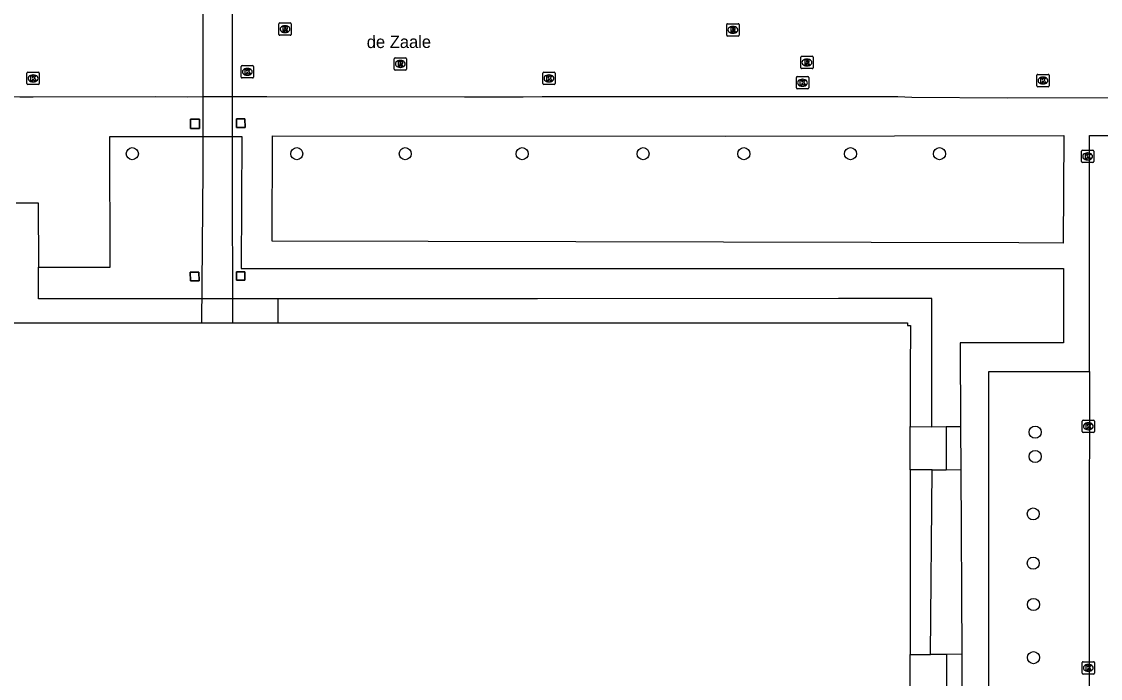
# Model space of a CAD drawing. Extents: x 161477 to 163040, y 383680 to 384868.
# Drawn here: x 161935.3 to 162022.7, y 384324.8 to 384378 of the extents above; entities that cross this region are included whole.
import ezdxf

# ---------------------------------------------------------------- set-up
doc = ezdxf.new("R2010")
doc.units = 0
for name, color, linetype in [('IMGEO_Boom', 7, 'Continuous'), ('IMGEO_Dek', 7, 'Continuous'), ('IMGEO_Groenvoorziening', 7, 'Continuous'), ('IMGEO_Kolk', 7, 'Continuous'), ('IMGEO_Openbare_ruimte_label', 7, 'Continuous'), ('IMGEO_Pand', 7, 'Continuous'), ('IMGEO_Pijler', 7, 'Continuous'), ('IMGEO_Rijbaan_lokaal_open', 7, 'Continuous'), ('IMGEO_Rioolput', 7, 'Continuous'), ('IMGEO_Voetpad_gesloten', 7, 'Continuous'), ('IMGEO_Voetpad_op_trap', 7, 'Continuous'), ('IMGEO_Voetpad_open', 7, 'Continuous')]:
    doc.layers.add(name, color=color, linetype=linetype)

msp = doc.modelspace()

# ---------------------------------------------------------------- linework, layer by layer
at = {"layer": 'IMGEO_Boom'}
for centre in [(161944.3, 384367.33), (161957.61, 384367.33), (161966.39, 384367.33), (161975.85, 384367.33), (161985.64, 384367.33), (161993.79, 384367.33), (162002.43, 384367.33), (162009.63, 384367.33), (162017.37, 384344.77), (162017.37, 384342.8), (162017.22, 384338.15), (162017.22, 384334.16), (162017.24, 384330.81), (162017.24, 384326.51)]:
    msp.add_circle(centre, 0.489, dxfattribs=at)
at = {"layer": 'IMGEO_Dek'}
msp.add_lwpolyline([(161952.4, 384381.825), (161952.383, 384398.52), (161949.962, 384398.52), (161949.996, 384381.818), (161950.004, 384371.924), (161950.007, 384368.834), (161950.009, 384366.051), (161949.91, 384353.629), (161952.428, 384353.629), (161952.416, 384366.048), (161952.413, 384368.836), (161952.41, 384371.927)], close=True, dxfattribs=at)
at = {"layer": 'IMGEO_Groenvoorziening'}
for points in [[(161949.701, 384357.043), (161948.998, 384357.039), (161948.994, 384357.742), (161949.697, 384357.746), (161949.701, 384357.043)], [(161953.419, 384357.087), (161952.733, 384357.084), (161952.73, 384357.77), (161953.416, 384357.773), (161953.419, 384357.087)], [(162009.022, 384345.215), (162009.008, 384355.596), (162001.453, 384355.609), (161977.095, 384355.578), (161956.091, 384355.586)], [(162008.905, 384326.757), (162009.025, 384341.729)]]:
    msp.add_lwpolyline(points, dxfattribs=at)
at = {"layer": 'IMGEO_Kolk'}
for p, q in [((161935.771, 384373.006), (161935.771, 384373.858)), ((161935.846, 384373.932), (161936.698, 384373.932)), ((161936.772, 384373.858), (161936.772, 384373.006)), ((161953.108, 384373.537), (161953.108, 384374.389)), ((161953.183, 384374.463), (161954.035, 384374.463)), ((161953.596, 384374.243), (161953.621, 384374.243)), ((161954.109, 384374.389), (161954.109, 384373.537)), ((161977.522, 384373.006), (161977.522, 384373.858)), ((161977.597, 384373.932), (161978.449, 384373.932)), ((161978.523, 384373.858), (161978.523, 384373.006)), ((161936.698, 384372.932), (161935.846, 384372.932)), ((161936.282, 384373.152), (161936.257, 384373.152)), ((161936.259, 384373.712), (161936.284, 384373.712)), ((161954.035, 384373.463), (161953.183, 384373.463)), ((161953.619, 384373.683), (161953.594, 384373.683)), ((161978.449, 384372.932), (161977.597, 384372.932)), ((161978.033, 384373.152), (161978.008, 384373.152)), ((161978.01, 384373.712), (161978.035, 384373.712)), ((161998.044, 384372.653), (161998.044, 384373.505)), ((161998.119, 384373.579), (161998.971, 384373.579)), ((161998.532, 384373.359), (161998.557, 384373.359)), ((161999.045, 384373.505), (161999.045, 384372.653)), ((162017.505, 384372.83), (162017.505, 384373.682)), ((162017.58, 384373.756), (162018.432, 384373.756)), ((162018.016, 384372.976), (162017.991, 384372.976)), ((162017.993, 384373.536), (162018.018, 384373.536)), ((162018.506, 384373.682), (162018.506, 384372.83)), ((161998.971, 384372.579), (161998.119, 384372.579)), ((161998.555, 384372.799), (161998.53, 384372.799)), ((162018.432, 384372.756), (162017.58, 384372.756)), ((162021.119, 384366.687), (162021.119, 384367.539)), ((162021.194, 384367.613), (162022.046, 384367.613)), ((162021.63, 384366.833), (162021.605, 384366.833)), ((162021.607, 384367.393), (162021.632, 384367.393)), ((162022.12, 384367.539), (162022.12, 384366.687)), ((162022.046, 384366.613), (162021.194, 384366.613)), ((162021.175, 384344.824), (162021.175, 384345.676)), ((162021.25, 384345.75), (162022.102, 384345.75)), ((162021.686, 384344.97), (162021.661, 384344.97)), ((162021.663, 384345.53), (162021.688, 384345.53)), ((162022.176, 384345.676), (162022.176, 384344.824)), ((162022.102, 384344.75), (162021.25, 384344.75)), ((162021.175, 384325.256), (162021.175, 384326.108)), ((162021.25, 384326.182), (162022.102, 384326.182)), ((162021.663, 384325.962), (162021.688, 384325.962)), ((162022.176, 384326.108), (162022.176, 384325.256)), ((162022.102, 384325.182), (162021.25, 384325.182)), ((162021.686, 384325.402), (162021.661, 384325.402))]:
    msp.add_line(p, q, dxfattribs=at)
for points in [[(161935.771, 384373.006), (161935.771, 384373.858)], [(161935.846, 384373.932), (161936.698, 384373.932)], [(161936.772, 384373.858), (161936.772, 384373.006)], [(161953.108, 384373.537), (161953.108, 384374.389)], [(161953.183, 384374.463), (161954.035, 384374.463)], [(161953.429, 384374.163), (161953.552, 384374.163), (161953.552, 384374.012), (161953.682, 384374.163), (161953.846, 384374.163), (161953.7, 384374.012), (161953.853, 384373.763), (161953.701, 384373.763), (161953.616, 384373.927), (161953.552, 384373.86), (161953.552, 384373.763), (161953.429, 384373.763), (161953.429, 384374.163)], [(161954.109, 384374.389), (161954.109, 384373.537)], [(161977.522, 384373.006), (161977.522, 384373.858)], [(161977.597, 384373.932), (161978.449, 384373.932)], [(161978.523, 384373.858), (161978.523, 384373.006)], [(161936.698, 384372.932), (161935.846, 384372.932)], [(161936.092, 384373.632), (161936.215, 384373.632), (161936.215, 384373.481), (161936.345, 384373.632), (161936.509, 384373.632), (161936.363, 384373.481), (161936.516, 384373.232), (161936.364, 384373.232), (161936.279, 384373.396), (161936.215, 384373.329), (161936.215, 384373.232), (161936.092, 384373.232), (161936.092, 384373.632)], [(161954.035, 384373.463), (161953.183, 384373.463)], [(161978.449, 384372.932), (161977.597, 384372.932)], [(161977.843, 384373.632), (161977.966, 384373.632), (161977.966, 384373.481), (161978.096, 384373.632), (161978.26, 384373.632), (161978.114, 384373.481), (161978.267, 384373.232), (161978.115, 384373.232), (161978.03, 384373.396), (161977.966, 384373.329), (161977.966, 384373.232), (161977.843, 384373.232), (161977.843, 384373.632)], [(161998.044, 384372.653), (161998.044, 384373.505)], [(161998.119, 384373.579), (161998.971, 384373.579)], [(161998.365, 384373.279), (161998.488, 384373.279), (161998.488, 384373.128), (161998.618, 384373.279), (161998.782, 384373.279), (161998.636, 384373.128), (161998.789, 384372.879), (161998.637, 384372.879), (161998.552, 384373.043), (161998.488, 384372.976), (161998.488, 384372.879), (161998.365, 384372.879), (161998.365, 384373.279)], [(161999.045, 384373.505), (161999.045, 384372.653)], [(162017.505, 384372.83), (162017.505, 384373.682)], [(162017.58, 384373.756), (162018.432, 384373.756)], [(162017.826, 384373.456), (162017.949, 384373.456), (162017.949, 384373.305), (162018.079, 384373.456), (162018.243, 384373.456), (162018.097, 384373.305), (162018.25, 384373.056), (162018.098, 384373.056), (162018.013, 384373.22), (162017.949, 384373.153), (162017.949, 384373.056), (162017.826, 384373.056), (162017.826, 384373.456)], [(162018.506, 384373.682), (162018.506, 384372.83)], [(161998.971, 384372.579), (161998.119, 384372.579)], [(162018.432, 384372.756), (162017.58, 384372.756)], [(162021.119, 384366.687), (162021.119, 384367.539)], [(162021.194, 384367.613), (162022.046, 384367.613)], [(162021.44, 384367.313), (162021.563, 384367.313), (162021.563, 384367.162), (162021.693, 384367.313), (162021.857, 384367.313), (162021.711, 384367.162), (162021.864, 384366.913), (162021.712, 384366.913), (162021.627, 384367.077), (162021.563, 384367.01), (162021.563, 384366.913), (162021.44, 384366.913), (162021.44, 384367.313)], [(162022.12, 384367.539), (162022.12, 384366.687)], [(162022.046, 384366.613), (162021.194, 384366.613)], [(162021.175, 384344.824), (162021.175, 384345.676)], [(162021.25, 384345.75), (162022.102, 384345.75)], [(162021.496, 384345.45), (162021.619, 384345.45), (162021.619, 384345.299), (162021.749, 384345.45), (162021.913, 384345.45), (162021.767, 384345.299), (162021.92, 384345.05), (162021.768, 384345.05), (162021.683, 384345.214), (162021.619, 384345.147), (162021.619, 384345.05), (162021.496, 384345.05), (162021.496, 384345.45)], [(162022.176, 384345.676), (162022.176, 384344.824)], [(162022.102, 384344.75), (162021.25, 384344.75)], [(162021.175, 384325.256), (162021.175, 384326.108)], [(162021.25, 384326.182), (162022.102, 384326.182)], [(162021.496, 384325.882), (162021.619, 384325.882), (162021.619, 384325.731), (162021.749, 384325.882), (162021.913, 384325.882), (162021.767, 384325.731), (162021.92, 384325.482), (162021.768, 384325.482), (162021.683, 384325.646), (162021.619, 384325.579), (162021.619, 384325.482), (162021.496, 384325.482), (162021.496, 384325.882)], [(162022.176, 384326.108), (162022.176, 384325.256)], [(162022.102, 384325.182), (162021.25, 384325.182)]]:
    msp.add_lwpolyline(points, dxfattribs=at)
for centre, start, end in [((161935.848, 384373.856), 91.55205, 178.44795), ((161935.848, 384373.856), 91.55205, 178.44795), ((161936.696, 384373.856), 1.55205, 88.44795), ((161936.696, 384373.856), 1.55205, 88.44795), ((161953.185, 384374.387), 91.55205, 178.44795), ((161953.185, 384374.387), 91.55205, 178.44795), ((161954.033, 384374.387), 1.55205, 88.44795), ((161954.033, 384374.387), 1.55205, 88.44795), ((161977.599, 384373.856), 91.55205, 178.44795), ((161977.599, 384373.856), 91.55205, 178.44795), ((161978.447, 384373.856), 1.55205, 88.44795), ((161978.447, 384373.856), 1.55205, 88.44795), ((161935.848, 384373.008), 181.55205, 268.44795), ((161935.848, 384373.008), 181.55205, 268.44795), ((161936.696, 384373.008), 271.55205, 358.44795), ((161936.696, 384373.008), 271.55205, 358.44795), ((161953.185, 384373.539), 181.55205, 268.44795), ((161953.185, 384373.539), 181.55205, 268.44795), ((161954.033, 384373.539), 271.55205, 358.44795), ((161954.033, 384373.539), 271.55205, 358.44795), ((161977.599, 384373.008), 181.55205, 268.44795), ((161977.599, 384373.008), 181.55205, 268.44795), ((161978.447, 384373.008), 271.55205, 358.44795), ((161978.447, 384373.008), 271.55205, 358.44795), ((161998.121, 384373.503), 91.55205, 178.44795), ((161998.121, 384373.503), 91.55205, 178.44795), ((161998.969, 384373.503), 1.55205, 88.44795), ((161998.969, 384373.503), 1.55205, 88.44795), ((162017.582, 384373.68), 91.55205, 178.44795), ((162017.582, 384373.68), 91.55205, 178.44795), ((162018.43, 384373.68), 1.55205, 88.44795), ((162018.43, 384373.68), 1.55205, 88.44795), ((161998.121, 384372.655), 181.55205, 268.44795), ((161998.121, 384372.655), 181.55205, 268.44795), ((161998.969, 384372.655), 271.55205, 358.44795), ((161998.969, 384372.655), 271.55205, 358.44795), ((162017.582, 384372.832), 181.55205, 268.44795), ((162017.582, 384372.832), 181.55205, 268.44795), ((162018.43, 384372.832), 271.55205, 358.44795), ((162018.43, 384372.832), 271.55205, 358.44795), ((162021.196, 384367.537), 91.55205, 178.44795), ((162021.196, 384367.537), 91.55205, 178.44795), ((162022.044, 384367.537), 1.55205, 88.44795), ((162022.044, 384367.537), 1.55205, 88.44795), ((162021.196, 384366.689), 181.55205, 268.44795), ((162021.196, 384366.689), 181.55205, 268.44795), ((162022.044, 384366.689), 271.55205, 358.44795), ((162022.044, 384366.689), 271.55205, 358.44795), ((162021.252, 384345.674), 91.55205, 178.44795), ((162021.252, 384345.674), 91.55205, 178.44795), ((162022.1, 384345.674), 1.55205, 88.44795), ((162022.1, 384345.674), 1.55205, 88.44795), ((162021.252, 384344.826), 181.55205, 268.44795), ((162021.252, 384344.826), 181.55205, 268.44795), ((162022.1, 384344.826), 271.55205, 358.44795), ((162022.1, 384344.826), 271.55205, 358.44795), ((162021.252, 384326.106), 91.55205, 178.44795), ((162021.252, 384326.106), 91.55205, 178.44795), ((162022.1, 384326.106), 1.55205, 88.44795), ((162022.1, 384326.106), 1.55205, 88.44795), ((162021.252, 384325.258), 181.55205, 268.44795), ((162021.252, 384325.258), 181.55205, 268.44795), ((162022.1, 384325.258), 271.55205, 358.44795), ((162022.1, 384325.258), 271.55205, 358.44795)]:
    msp.add_arc(centre, 0.0765, start, end, dxfattribs=at)
for centre, major_axis, ratio, start_param, end_param in [((161953.595, 384373.963), (-0.387, 0.002), 0.722429, 4.712389, 7.853982), ((161953.62, 384373.963), (-0.39, 0.002), 0.717154, 1.570796, 4.712389), ((161936.258, 384373.432), (-0.387, 0.002), 0.722429, 4.712389, 7.853982), ((161936.283, 384373.432), (-0.39, 0.002), 0.717154, 1.570796, 4.712389), ((161978.009, 384373.432), (-0.387, 0.002), 0.722429, 4.712389, 7.853982), ((161978.034, 384373.432), (-0.39, 0.002), 0.717154, 1.570796, 4.712389), ((161998.531, 384373.079), (-0.387, 0.002), 0.722429, 4.712389, 7.853982), ((161998.556, 384373.079), (-0.39, 0.002), 0.717154, 1.570796, 4.712389), ((162017.992, 384373.256), (-0.387, 0.002), 0.722429, 4.712389, 7.853982), ((162018.017, 384373.256), (-0.39, 0.002), 0.717154, 1.570796, 4.712389), ((162021.606, 384367.113), (-0.387, 0.002), 0.722429, 4.712389, 7.853982), ((162021.631, 384367.113), (-0.39, 0.002), 0.717154, 1.570796, 4.712389), ((162021.662, 384345.25), (-0.387, 0.002), 0.722429, 4.712389, 7.853982), ((162021.687, 384345.25), (-0.39, 0.002), 0.717154, 1.570796, 4.712389), ((162021.662, 384325.682), (-0.387, 0.002), 0.722429, 4.712389, 7.853982), ((162021.687, 384325.682), (-0.39, 0.002), 0.717154, 1.570796, 4.712389)]:
    msp.add_ellipse(centre, major_axis=major_axis, ratio=ratio, start_param=start_param, end_param=end_param, dxfattribs=at)
at = {"layer": 'IMGEO_Pand'}
for points in [[(161931.099, 384345.216), (161931.099, 384353.639), (161933.893, 384353.637), (161948.675, 384353.629), (161949.91, 384353.629), (161952.428, 384353.629), (161956.079, 384353.629)], [(161956.079, 384353.629), (161975.929, 384353.631), (161979.971, 384353.637), (162000, 384353.638), (162007.041, 384353.639), (162007.041, 384353.409), (162007.271, 384353.409), (162007.254, 384349.615), (162007.258, 384345.226)], [(162007.261, 384341.729), (162007.258, 384345.226)], [(162007.261, 384341.729), (162007.264, 384338.471), (162007.264, 384334.854), (162007.264, 384334.654), (162007.264, 384332.414), (162007.264, 384332.234), (162007.264, 384326.758)], [(162007.264, 384323.034), (162007.264, 384326.758)]]:
    msp.add_lwpolyline(points, dxfattribs=at)
at = {"layer": 'IMGEO_Pijler'}
for points in [[(161949.741, 384370.124), (161948.998, 384370.12), (161949.002, 384369.377), (161949.745, 384369.381)], [(161953.414, 384370.152), (161952.72, 384370.142), (161952.73, 384369.448), (161953.424, 384369.458)], [(161949.697, 384357.746), (161948.994, 384357.742), (161948.998, 384357.039), (161949.701, 384357.043)], [(161953.419, 384357.087), (161953.416, 384357.773), (161952.73, 384357.77), (161952.733, 384357.084)]]:
    msp.add_lwpolyline(points, close=True, dxfattribs=at)
at = {"layer": 'IMGEO_Rijbaan_lokaal_open'}
for points in [[(162041.294, 384371.87), (162015.132, 384371.834), (162007.404, 384371.892), (162006.247, 384371.928), (162000, 384371.926), (161998.045, 384371.925), (161977.467, 384371.944), (161975.939, 384371.915), (161971.175, 384371.919), (161955.193, 384371.931), (161952.41, 384371.927), (161950.004, 384371.924), (161948.753, 384371.922), (161946.163, 384371.925), (161936.279, 384371.91), (161935.201, 384371.899), (161908.29, 384371.964), (161891.226, 384371.987)], [(162021.759, 384349.699), (162021.759, 384368.798), (162027.862, 384368.791), (162027.862, 384282.06), (162027.95, 384253.54)], [(162021.759, 384349.699), (162021.737, 384335.473), (162021.757, 384295.008)]]:
    msp.add_lwpolyline(points, dxfattribs=at)
at = {"layer": 'IMGEO_Rioolput'}
for p, q in [((161956.159, 384376.994), (161956.159, 384377.846)), ((161956.234, 384377.92), (161957.086, 384377.92)), ((161956.647, 384377.7), (161956.672, 384377.7)), ((161957.16, 384377.846), (161957.16, 384376.994)), ((161992.409, 384376.934), (161992.409, 384377.786)), ((161992.484, 384377.86), (161993.336, 384377.86)), ((161992.897, 384377.64), (161992.922, 384377.64)), ((161993.41, 384377.786), (161993.41, 384376.934)), ((161957.086, 384376.92), (161956.234, 384376.92)), ((161956.67, 384377.14), (161956.645, 384377.14)), ((161993.336, 384376.86), (161992.484, 384376.86)), ((161992.92, 384377.08), (161992.895, 384377.08)), ((161965.489, 384374.174), (161965.489, 384375.026)), ((161965.564, 384375.1), (161966.416, 384375.1)), ((161965.977, 384374.88), (161966.002, 384374.88)), ((161966.49, 384375.026), (161966.49, 384374.174)), ((161998.399, 384374.294), (161998.399, 384375.146)), ((161998.474, 384375.22), (161999.326, 384375.22)), ((161998.887, 384375), (161998.912, 384375)), ((161999.4, 384375.146), (161999.4, 384374.294)), ((161966.416, 384374.1), (161965.564, 384374.1)), ((161966, 384374.32), (161965.975, 384374.32)), ((161999.326, 384374.22), (161998.474, 384374.22)), ((161998.91, 384374.44), (161998.885, 384374.44))]:
    msp.add_line(p, q, dxfattribs=at)
for points in [[(161956.159, 384376.994), (161956.159, 384377.846)], [(161956.234, 384377.92), (161957.086, 384377.92)], [(161956.748, 384377.618), (161956.496, 384377.62), (161956.496, 384377.22)], [(161956.496, 384377.22), (161956.62, 384377.22), (161956.62, 384377.382), (161956.631, 384377.382)], [(161956.674, 384377.539), (161956.62, 384377.539), (161956.62, 384377.458)], [(161956.62, 384377.458), (161956.672, 384377.458)], [(161956.678, 384377.353), (161956.749, 384377.22), (161956.889, 384377.22), (161956.824, 384377.346)], [(161957.16, 384377.846), (161957.16, 384376.994)], [(161992.409, 384376.934), (161992.409, 384377.786)], [(161992.484, 384377.86), (161993.336, 384377.86)], [(161992.998, 384377.558), (161992.746, 384377.56), (161992.746, 384377.16)], [(161992.746, 384377.16), (161992.87, 384377.16), (161992.87, 384377.322), (161992.881, 384377.322)], [(161992.924, 384377.479), (161992.87, 384377.479), (161992.87, 384377.398)], [(161992.87, 384377.398), (161992.922, 384377.398)], [(161992.928, 384377.293), (161992.999, 384377.16), (161993.139, 384377.16), (161993.074, 384377.286)], [(161993.41, 384377.786), (161993.41, 384376.934)], [(161957.086, 384376.92), (161956.234, 384376.92)], [(161993.336, 384376.86), (161992.484, 384376.86)], [(161965.489, 384374.174), (161965.489, 384375.026)], [(161965.564, 384375.1), (161966.416, 384375.1)], [(161966.078, 384374.798), (161965.826, 384374.8), (161965.826, 384374.4)], [(161966.004, 384374.719), (161965.95, 384374.719), (161965.95, 384374.638)], [(161966.49, 384375.026), (161966.49, 384374.174)], [(161998.399, 384374.294), (161998.399, 384375.146)], [(161998.474, 384375.22), (161999.326, 384375.22)], [(161998.988, 384374.918), (161998.736, 384374.92), (161998.736, 384374.52)], [(161998.736, 384374.52), (161998.86, 384374.52), (161998.86, 384374.682), (161998.871, 384374.682)], [(161998.914, 384374.839), (161998.86, 384374.839), (161998.86, 384374.758)], [(161998.86, 384374.758), (161998.912, 384374.758)], [(161999.4, 384375.146), (161999.4, 384374.294)], [(161966.416, 384374.1), (161965.564, 384374.1)], [(161965.826, 384374.4), (161965.95, 384374.4), (161965.95, 384374.562), (161965.961, 384374.562)], [(161965.95, 384374.638), (161966.002, 384374.638)], [(161966.008, 384374.533), (161966.079, 384374.4), (161966.219, 384374.4), (161966.154, 384374.526)], [(161999.326, 384374.22), (161998.474, 384374.22)], [(161998.918, 384374.653), (161998.989, 384374.52), (161999.129, 384374.52), (161999.064, 384374.646)]]:
    msp.add_lwpolyline(points, dxfattribs=at)
for centre, radius, start, end in [((161956.236, 384377.844), 0.0765, 91.55205, 178.44795), ((161956.236, 384377.844), 0.0765, 91.55205, 178.44795), ((161956.63, 384377.329), 0.0533, 26.02933, 88.69889), ((161956.656, 384377.647), 0.19, 274.7715, 282.96867), ((161956.68, 384377.443), 0.0964, 77.00612, 93.18647), ((161956.694, 384377.5), 0.0378, 276.66336, 79.67722), ((161956.747, 384377.508), 0.109, 350.36119, 89.41601), ((161956.745, 384377.508), 0.112, 277.58423, 350.98172), ((161956.729, 384377.293), 0.108, 29.51342, 73.79051), ((161957.084, 384377.844), 0.0765, 1.55205, 88.44795), ((161957.084, 384377.844), 0.0765, 1.55205, 88.44795), ((161992.486, 384377.784), 0.0765, 91.55205, 178.44795), ((161992.486, 384377.784), 0.0765, 91.55205, 178.44795), ((161992.88, 384377.269), 0.0533, 26.02933, 88.69889), ((161992.906, 384377.587), 0.19, 274.7715, 282.96867), ((161992.93, 384377.383), 0.0964, 77.00612, 93.18647), ((161992.944, 384377.44), 0.0378, 276.66336, 79.67722), ((161992.997, 384377.448), 0.109, 350.36119, 89.41601), ((161992.995, 384377.448), 0.112, 277.58423, 350.98172), ((161992.979, 384377.233), 0.108, 29.51342, 73.79051), ((161993.334, 384377.784), 0.0765, 1.55205, 88.44795), ((161993.334, 384377.784), 0.0765, 1.55205, 88.44795), ((161956.236, 384376.996), 0.0765, 181.55205, 268.44795), ((161956.236, 384376.996), 0.0765, 181.55205, 268.44795), ((161957.084, 384376.996), 0.0765, 271.55205, 358.44795), ((161957.084, 384376.996), 0.0765, 271.55205, 358.44795), ((161992.486, 384376.936), 0.0765, 181.55205, 268.44795), ((161992.486, 384376.936), 0.0765, 181.55205, 268.44795), ((161993.334, 384376.936), 0.0765, 271.55205, 358.44795), ((161993.334, 384376.936), 0.0765, 271.55205, 358.44795), ((161965.566, 384375.024), 0.0765, 91.55205, 178.44795), ((161965.566, 384375.024), 0.0765, 91.55205, 178.44795), ((161966.01, 384374.623), 0.0964, 77.00612, 93.18647), ((161966.024, 384374.68), 0.0378, 276.66336, 79.67722), ((161966.077, 384374.688), 0.109, 350.36119, 89.41601), ((161966.075, 384374.688), 0.112, 277.58423, 350.98172), ((161966.414, 384375.024), 0.0765, 1.55205, 88.44795), ((161966.414, 384375.024), 0.0765, 1.55205, 88.44795), ((161998.476, 384375.144), 0.0765, 91.55205, 178.44795), ((161998.476, 384375.144), 0.0765, 91.55205, 178.44795), ((161998.87, 384374.629), 0.0533, 26.02933, 88.69889), ((161998.896, 384374.947), 0.19, 274.7715, 282.96867), ((161998.92, 384374.743), 0.0964, 77.00612, 93.18647), ((161998.934, 384374.8), 0.0378, 276.66336, 79.67722), ((161998.987, 384374.808), 0.109, 350.36119, 89.41601), ((161998.985, 384374.808), 0.112, 277.58423, 350.98172), ((161998.969, 384374.593), 0.108, 29.51342, 73.79051), ((161999.324, 384375.144), 0.0765, 1.55205, 88.44795), ((161999.324, 384375.144), 0.0765, 1.55205, 88.44795), ((161965.566, 384374.176), 0.0765, 181.55205, 268.44795), ((161965.566, 384374.176), 0.0765, 181.55205, 268.44795), ((161965.96, 384374.509), 0.0533, 26.02933, 88.69889), ((161965.986, 384374.827), 0.19, 274.7715, 282.96867), ((161966.059, 384374.473), 0.108, 29.51342, 73.79051), ((161966.414, 384374.176), 0.0765, 271.55205, 358.44795), ((161966.414, 384374.176), 0.0765, 271.55205, 358.44795), ((161998.476, 384374.296), 0.0765, 181.55205, 268.44795), ((161998.476, 384374.296), 0.0765, 181.55205, 268.44795), ((161999.324, 384374.296), 0.0765, 271.55205, 358.44795), ((161999.324, 384374.296), 0.0765, 271.55205, 358.44795)]:
    msp.add_arc(centre, radius, start, end, dxfattribs=at)
for centre, major_axis, ratio, start_param, end_param in [((161956.646, 384377.42), (-0.387, 0.002), 0.722429, 4.712389, 7.853982), ((161956.671, 384377.42), (-0.39, 0.002), 0.717154, 1.570796, 4.712389), ((161992.896, 384377.36), (-0.387, 0.002), 0.722429, 4.712389, 7.853982), ((161992.921, 384377.36), (-0.39, 0.002), 0.717154, 1.570796, 4.712389), ((161965.976, 384374.6), (-0.387, 0.002), 0.722429, 4.712389, 7.853982), ((161966.001, 384374.6), (-0.39, 0.002), 0.717154, 1.570796, 4.712389), ((161998.886, 384374.72), (-0.387, 0.002), 0.722429, 4.712389, 7.853982), ((161998.911, 384374.72), (-0.39, 0.002), 0.717154, 1.570796, 4.712389)]:
    msp.add_ellipse(centre, major_axis=major_axis, ratio=ratio, start_param=start_param, end_param=end_param, dxfattribs=at)
at = {"layer": 'IMGEO_Voetpad_gesloten'}
msp.add_lwpolyline([(161952.383, 384398.52), (161949.962, 384398.52), (161949.996, 384381.818), (161950.004, 384371.924), (161950.007, 384368.834), (161950.009, 384366.051), (161949.91, 384353.629), (161952.428, 384353.629), (161952.416, 384366.048), (161952.413, 384368.836), (161952.41, 384371.927), (161952.4, 384381.825), (161952.383, 384398.52)], dxfattribs=at)
at = {"layer": 'IMGEO_Voetpad_op_trap'}
for points in [[(162010.176, 384345.22), (162011.33, 384345.226)], [(162010.178, 384341.736), (162011.351, 384341.744)], [(162011.445, 384326.784), (162010.185, 384326.771)]]:
    msp.add_lwpolyline(points, dxfattribs=at)
at = {"layer": 'IMGEO_Voetpad_open'}
for points in [[(161949.002, 384369.377), (161948.998, 384370.12), (161949.741, 384370.124), (161949.745, 384369.381), (161949.002, 384369.377)], [(161952.73, 384369.448), (161952.72, 384370.142), (161953.414, 384370.152), (161953.424, 384369.458), (161952.73, 384369.448)], [(161936.694, 384358.138), (161942.498, 384358.139), (161942.482, 384368.727), (161942.862, 384368.728), (161953.158, 384368.717), (161953.117, 384358.025), (162019.655, 384358.031), (162019.67, 384351.998), (162011.295, 384352.003), (162011.33, 384345.226)], [(161968.257, 384360.218), (161955.624, 384360.236), (161955.635, 384368.786), (161992.273, 384368.761), (162019.688, 384368.801), (162019.646, 384360.078), (162016.041, 384360.119), (161968.257, 384360.218)], [(161934.901, 384363.352), (161936.693, 384363.35), (161936.694, 384358.138)], [(161956.091, 384355.586), (161952.426, 384355.581), (161949.926, 384355.581), (161936.694, 384355.581), (161936.694, 384358.138)], [(161956.091, 384355.586), (161956.079, 384353.629)], [(162013.608, 384285.103), (162013.678, 384294.936), (162013.613, 384324.033), (162013.626, 384349.696), (162021.759, 384349.699)], [(162007.258, 384345.226), (162009.022, 384345.215)], [(162009.022, 384345.215), (162010.176, 384345.22)], [(162010.176, 384345.22), (162010.178, 384341.736)], [(162011.33, 384345.226), (162011.351, 384341.744)], [(162009.025, 384341.729), (162007.261, 384341.729)], [(162009.025, 384341.729), (162010.178, 384341.736)], [(162011.351, 384341.744), (162011.445, 384326.784)], [(162007.264, 384326.758), (162008.905, 384326.757)], [(162010.185, 384326.771), (162008.905, 384326.757)], [(162010.185, 384326.771), (162010.186, 384323.028)], [(162011.445, 384326.784), (162011.446, 384326.621), (162011.438, 384323.025)]]:
    msp.add_lwpolyline(points, dxfattribs=at)

# ---------------------------------------------------------------- texts
at = {"layer": 'IMGEO_Openbare_ruimte_label'}
msp.add_text('de Zaale', height=1, rotation=0.11459, dxfattribs=at).set_placement((161963.277, 384375.885))

doc.saveas('drawing.dxf')
